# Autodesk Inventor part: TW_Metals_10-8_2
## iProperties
Shininess: 64.0
Length Units: 11272
Angle Units: 11279
Time Units: 11290
Mass Units: 11286
Length Display Precision: 3
Angle Display Precision: 2
Compacted: True
Part Number: TW_Metals_10-8_2
Document SubType Name: Modeling
Created: 2005-05
Designer: John Blackburn
Material: Aluminum-6061
Manufacturer: Standard
Standards Organization: Custom
Density: 0.0
Volumn: 0.0
Area: 0.0
PropertySet Name: Model Information
Control State: 0
Master: False
Checked Out: False
Author: John Blackburn
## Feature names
1. Extrusion1
2. Hole2
3. Chamfer1
